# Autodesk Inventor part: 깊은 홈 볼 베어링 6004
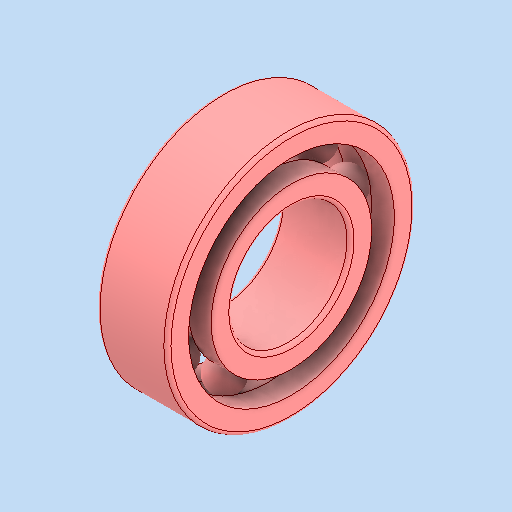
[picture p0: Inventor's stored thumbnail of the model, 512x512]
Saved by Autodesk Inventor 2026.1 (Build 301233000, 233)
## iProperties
Created: 2025-11
Part Number: 깊은 홈 볼 베어링 6004
Material: 강철, 연강
Description: 깊은 그루브 볼 베어링
Document SubType Name: Modeling
Designer: PC-30
Density: 7.85 g/cm^3
Appearance: 기본값
Author: jhkim
Sending System: Autodesk Inventor 2026
Preprocessor: ST-DEVELOPER v20.1
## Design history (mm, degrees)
feature "Solid1"
feature "Solid1:1"
feature "Solid1:2"
feature "Solid1:3"
feature "Solid1:4"
feature "Solid1:5"
feature "Solid1:6"
feature "Solid1:7"
feature "Solid1:8"
feature "Solid1:9"
feature "Solid1:10"
node "솔리드1"
node "솔리드2"
node "솔리드3"
node "솔리드4"
node "솔리드5"
node "솔리드6"
node "솔리드7"
node "솔리드8"
node "솔리드9"
node "솔리드10"
node "솔리드11"
